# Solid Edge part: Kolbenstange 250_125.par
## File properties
Username: ahadarics
Dokumentum tartalom típus: 0
Author: ahadarics
Last saved by: ahadarics
Revision: 83
Sűrűség: 0,000 kg/m^3
Pontosság: 0,990
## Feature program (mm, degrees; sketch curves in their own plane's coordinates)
base feature "unnamed BaseFeature 1"
thread "unnamed Thread 1"
chamfer "Letörés_1"  SetBackValue2 = 20 deg
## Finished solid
Body 1: solid body, 19 faces, 27 edges, 11 vertices.
  Faces by surface: plane 8, cylinder 5, cone 3, torus 3
  Edges by curve: circle 15, line 7, curve on surface 3, ellipse 2
Bounding box of the edges (mm; curved faces can reach further): 250.000 x 250.000 x 454.000, from (-125, -125, -197) to (125, 125, 257).
Cylindrical faces by radius (mm): R19.4 x1, R21 x1, R24.5 x1, R25 x1, R125 x1
Conical faces (half-angle, radius in mm at the cone's reference point): 20 deg R21 x1, 30 deg R24.75 x1, 60 deg R20.2 x1
Toroidal faces (ring radius, tube radius in mm): R20.2 r0.8 x2, R22.5 r2 x1
Planar faces by outward normal: +x 1, +z 3, -x 1, -z 1, oblique 2
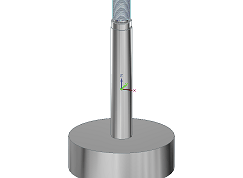
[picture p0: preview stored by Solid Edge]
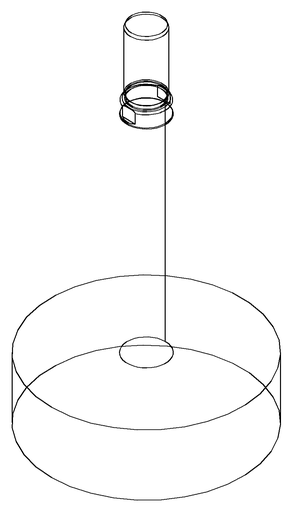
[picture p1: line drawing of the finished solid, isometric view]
